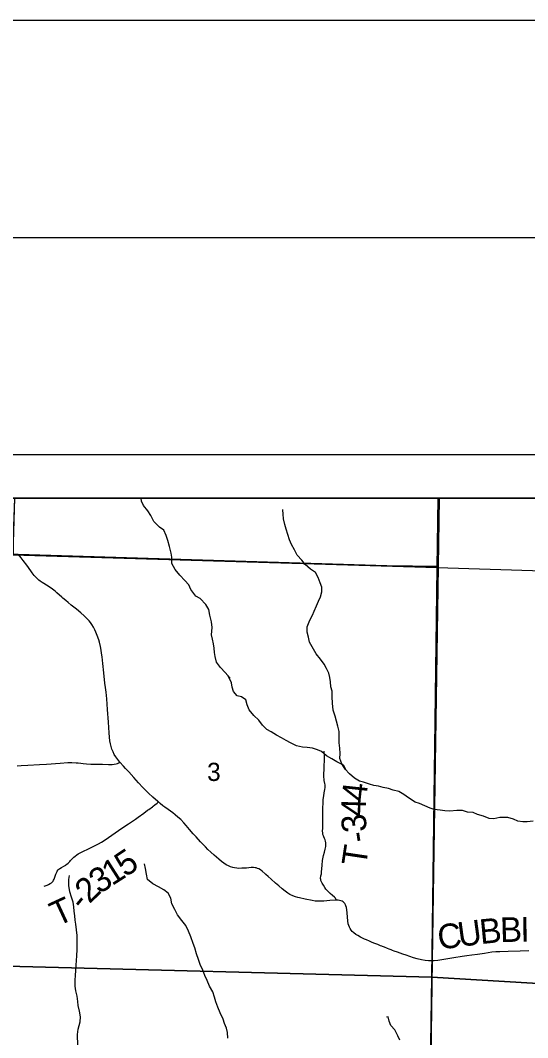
# Model space of a CAD drawing. Extents: x 0 to 34, y 0 to 22.
# Drawn here: x 24.137 to 25.305, y 19.658 to 22 of the extents above; entities that cross this region are included whole.
import ezdxf

# ---------------------------------------------------------------- set-up
doc = ezdxf.new("R2010")
doc.units = 0
for name, color, linetype in [('GM_X_Corporation', 7, 'Continuous'), ('GM_X_County_Road', 7, 'Continuous'), ('GM_X_County_Road_Text', 7, 'Continuous'), ('GM_X_Minor_River', 7, 'Continuous'), ('GM_X_Section_Text', 7, 'Continuous'), ('GM_X_Township_Road', 7, 'Continuous'), ('GM_X_Township_Road_Text', 7, 'Continuous'), ('SH_Border', 7, 'Continuous'), ('SH_Cut_Line', 7, 'Continuous'), ('SH_Data', 7, 'Continuous')]:
    doc.layers.add(name, color=color, linetype=linetype)

msp = doc.modelspace()

# ---------------------------------------------------------------- linework, layer by layer
at = {"layer": 'GM_X_Corporation'}
for points in [[(30.3167, 20.9), (23.5167, 20.9), (23.5167, 14.7114), (24.6586, 14.6808), (24.6805, 14.6799), (26.0522, 14.6391), (26.4447, 14.6283), (26.4468, 14.6272), (26.4498, 14.6263), (26.4544, 14.6257), (26.5226, 14.6248), (26.5325, 14.6248), (26.5616, 14.6241), (26.5684, 14.624), (26.5727, 14.624), (26.5813, 14.6239), (26.5991, 14.6234), (26.6128, 14.6229), (26.6208, 14.6225), (26.6337, 14.622), (26.643, 14.6216), (26.6535, 14.621), (27.01, 14.6164)], [(30.3167, 20.9), (25.1014, 20.9), (25.0988, 20.7425), (25.0847, 19.8351), (25.0701, 18.7696), (25.0668, 18.5474), (25.0619, 17.7438), (25.4012, 17.7333), (26.0747, 17.7146), (26.0759, 17.6934), (26.0745, 17.4524), (26.0677, 16.948), (26.0646, 16.863), (26.0683, 16.6823), (26.3378, 16.673), (27.0694, 16.6556)], [(26.0759, 17.6934), (26.0747, 17.7146), (25.4012, 17.7333), (25.0619, 17.7438), (25.0668, 18.5474), (25.0701, 18.7696), (25.0847, 19.8351), (25.0988, 20.7425), (24.9808, 20.7443), (24.1323, 20.7702), (24.1208, 20.7707), (23.5167, 20.7862), (23.5167, 14.7114)]]:
    msp.add_lwpolyline(points, dxfattribs=at)
for points in [[(25.0987, 20.9), (24.1235, 20.9), (24.1192, 20.7694), (25.0966, 20.7402)], [(25.1014, 20.9), (24.124, 20.9), (24.1207, 20.7979), (24.1208, 20.7707), (24.1323, 20.7702), (24.9808, 20.7443), (25.0988, 20.7425)], [(26.1019, 20.9), (25.0987, 20.9), (25.0966, 20.7402), (26.0969, 20.7089)], [(24.0752, 20.7675), (24.1192, 20.7694), (25.0966, 20.7402), (25.0844, 19.7972), (24.0758, 19.8228)], [(26.0969, 20.7089), (26.1216, 20.708), (26.1009, 19.7362), (25.0844, 19.7972), (25.0966, 20.7402)], [(25.0844, 19.7972), (25.0685, 18.7697), (24.0555, 18.7938), (24.0758, 19.8228)], [(25.0844, 19.7972), (26.1009, 19.7362), (26.0916, 18.7368), (25.0685, 18.7697)]]:
    msp.add_lwpolyline(points, close=True, dxfattribs=at)
at = {"layer": 'GM_X_County_Road'}
for points in [[(24.366, 20.2916), (24.3612, 20.2977), (24.3589, 20.3009), (24.3569, 20.304), (24.3534, 20.3099), (24.3504, 20.3159), (24.3478, 20.3221), (24.3458, 20.3279), (24.3443, 20.3339), (24.343, 20.3411), (24.342, 20.3497), (24.3412, 20.3596), (24.3405, 20.372), (24.3399, 20.3838), (24.338, 20.4129), (24.336, 20.4376), (24.3343, 20.453), (24.3331, 20.4635), (24.3319, 20.474), (24.3293, 20.4975), (24.3271, 20.5191), (24.3252, 20.5345), (24.3242, 20.5432), (24.3232, 20.5499), (24.3214, 20.5585), (24.319, 20.5681), (24.3174, 20.5735), (24.3141, 20.5836), (24.3111, 20.5912), (24.3088, 20.5963), (24.3055, 20.6024), (24.3016, 20.6088), (24.2983, 20.6134), (24.2952, 20.6173), (24.2901, 20.6228), (24.2843, 20.6285), (24.2765, 20.6355), (24.2664, 20.6438), (24.2544, 20.6536), (24.2472, 20.6594), (24.2414, 20.664), (24.2352, 20.6692), (24.2324, 20.6717), (24.221, 20.6821), (24.2172, 20.6853), (24.2113, 20.69), (24.2059, 20.6941), (24.1976, 20.6997), (24.1912, 20.7035), (24.1875, 20.7058), (24.1828, 20.7087), (24.1794, 20.7113), (24.1758, 20.7145), (24.1732, 20.7171), (24.1692, 20.7217), (24.1643, 20.728), (24.1543, 20.7423), (24.1513, 20.7462), (24.1499, 20.7483), (24.1482, 20.7502), (24.1445, 20.7552), (24.1437, 20.7561), (24.1386, 20.7624), (24.1325, 20.7697)], [(24.4547, 20.2003), (24.4533, 20.2014), (24.4422, 20.2113), (24.4323, 20.2206), (24.4261, 20.2267), (24.4192, 20.2338), (24.4091, 20.2446), (24.3983, 20.2565), (24.3865, 20.2693), (24.3792, 20.2775), (24.3743, 20.2829), (24.366, 20.2916)], [(24.8645, 19.9742), (24.8496, 19.9733), (24.836, 19.972), (24.8267, 19.9716), (24.8218, 19.9716), (24.8157, 19.972), (24.8084, 19.973), (24.7926, 19.9763), (24.7793, 19.9793), (24.7757, 19.9803), (24.7705, 19.9819), (24.7641, 19.9844), (24.7574, 19.9874), (24.7527, 19.9902), (24.7468, 19.9946), (24.7396, 20.0005), (24.7321, 20.0069), (24.7247, 20.0135), (24.7145, 20.0227), (24.7075, 20.0289), (24.7024, 20.0334), (24.7005, 20.035), (24.6935, 20.0412), (24.6899, 20.0439), (24.6861, 20.0462), (24.6832, 20.0474), (24.6801, 20.0484), (24.6776, 20.0488), (24.6738, 20.0491), (24.6687, 20.049), (24.6575, 20.0481), (24.647, 20.0475), (24.6402, 20.0474), (24.6354, 20.0478), (24.6299, 20.0486), (24.6258, 20.0496), (24.6211, 20.0512), (24.616, 20.0533), (24.6111, 20.0558), (24.6053, 20.0593), (24.5998, 20.0632), (24.5936, 20.0683), (24.5829, 20.0777), (24.5756, 20.0845), (24.569, 20.091), (24.5629, 20.0972), (24.5521, 20.1083), (24.5416, 20.1198), (24.5351, 20.1272), (24.5266, 20.1371), (24.5189, 20.1461), (24.5131, 20.1525), (24.5062, 20.1597), (24.4998, 20.1656), (24.4937, 20.1709), (24.4879, 20.1755), (24.4773, 20.1829), (24.4698, 20.1883), (24.4653, 20.1917), (24.4586, 20.197), (24.4547, 20.2003)], [(25.3077, 19.8572), (25.2872, 19.8567), (25.2599, 19.8561), (25.2407, 19.8555), (25.2314, 19.8549), (25.2226, 19.8541), (25.2136, 19.8528), (25.2058, 19.8516), (25.1893, 19.8493), (25.1764, 19.8474), (25.1647, 19.8456), (25.1542, 19.8442), (25.1352, 19.8413), (25.126, 19.8399), (25.1076, 19.8368), (25.0978, 19.8354), (25.0898, 19.8347), (25.0849, 19.8345), (25.0831, 19.8345), (25.0763, 19.8347), (25.069, 19.8354), (25.0604, 19.8368), (25.0508, 19.8391), (25.0419, 19.8417), (25.0336, 19.8443), (25.0249, 19.8474), (25.0178, 19.8498), (25.005, 19.8543), (24.9975, 19.857), (24.994, 19.8584), (24.9922, 19.859), (24.9905, 19.8597), (24.9859, 19.8615), (24.9819, 19.8631), (24.975, 19.8658), (24.971, 19.8675), (24.9693, 19.8681), (24.9664, 19.8692), (24.9646, 19.8699), (24.96, 19.8717), (24.9554, 19.8735), (24.9508, 19.8754), (24.9451, 19.8777), (24.9405, 19.8796), (24.9336, 19.8825), (24.9291, 19.8845), (24.9258, 19.8861), (24.9197, 19.8891), (24.9137, 19.8924), (24.909, 19.8953), (24.9046, 19.8986), (24.9011, 19.9019), (24.8983, 19.9051), (24.896, 19.9087), (24.8944, 19.9119), (24.893, 19.9159), (24.892, 19.92), (24.891, 19.9267), (24.8902, 19.9347), (24.8894, 19.9447), (24.8887, 19.9515), (24.8877, 19.9571), (24.8866, 19.9608), (24.8854, 19.9637), (24.8836, 19.9665), (24.8819, 19.9684), (24.8799, 19.9701), (24.8776, 19.9715), (24.8746, 19.9728), (24.872, 19.9737), (24.8686, 19.9742), (24.8645, 19.9742)]]:
    msp.add_lwpolyline(points, dxfattribs=at)
at = {"layer": 'GM_X_Minor_River'}
for points in [[(24.6198, 20.4855), (24.6083, 20.4983), (24.5976, 20.51), (24.5884, 20.5225), (24.5857, 20.535), (24.5841, 20.5444), (24.5833, 20.5543), (24.5813, 20.5642), (24.579, 20.5748), (24.577, 20.585), (24.5788, 20.6021), (24.5768, 20.6154), (24.5733, 20.6306), (24.5709, 20.6435), (24.5644, 20.6552), (24.5506, 20.6688), (24.5411, 20.6744), (24.5292, 20.6891), (24.525, 20.7001), (24.5155, 20.7099), (24.5044, 20.7224), (24.4933, 20.7352), (24.486, 20.7496), (24.4859, 20.764), (24.4843, 20.7735), (24.4804, 20.7887), (24.4765, 20.8023), (24.4726, 20.8137), (24.4676, 20.8258), (24.457, 20.8333), (24.4444, 20.8458), (24.4371, 20.8598), (24.4302, 20.8704), (24.4206, 20.8832), (24.4163, 20.8931), (24.4155, 20.9)], [(24.8307, 20.6841), (24.8314, 20.6951), (24.8271, 20.7049), (24.8229, 20.7174), (24.8167, 20.7287), (24.8053, 20.7361), (24.7927, 20.747), (24.7847, 20.7571), (24.7744, 20.7688), (24.7679, 20.7805), (24.7613, 20.7929), (24.7563, 20.8038), (24.7524, 20.8163), (24.7489, 20.8284), (24.7462, 20.8394), (24.7426, 20.8522), (24.7418, 20.8628), (24.7409, 20.8731), (24.7413, 20.8738)], [(25.3174, 20.156), (25.3038, 20.1547), (25.2939, 20.1542), (25.2818, 20.1564), (25.272, 20.1608), (25.2591, 20.1645), (25.2406, 20.1643), (25.227, 20.1615), (25.216, 20.1625), (25.2035, 20.1673), (25.1895, 20.1713), (25.1796, 20.1761), (25.166, 20.1764), (25.1546, 20.1804), (25.1418, 20.1807), (25.1255, 20.1794), (25.1145, 20.18), (25.1032, 20.1814), (25.0899, 20.1832), (25.0801, 20.1857), (25.0679, 20.1916), (25.0562, 20.1964), (25.046, 20.1994), (25.0307, 20.2098), (25.0197, 20.2177), (25.0079, 20.224), (24.9954, 20.2273), (24.9844, 20.2309), (24.9719, 20.2338), (24.9617, 20.2368), (24.9507, 20.2385), (24.9405, 20.2415), (24.9272, 20.2459), (24.9174, 20.2484), (24.9063, 20.2551), (24.8949, 20.2652), (24.885, 20.2757), (24.8769, 20.2882), (24.8727, 20.3002), (24.873, 20.312), (24.8721, 20.3241), (24.8712, 20.3366), (24.8707, 20.3499), (24.8706, 20.3624), (24.8682, 20.3745), (24.8647, 20.3866), (24.862, 20.3975), (24.857, 20.4119), (24.8557, 20.4278), (24.8548, 20.4425), (24.8547, 20.455), (24.8519, 20.4653), (24.8511, 20.4766), (24.8495, 20.4865), (24.8471, 20.497), (24.8421, 20.5072), (24.8364, 20.5174), (24.8276, 20.5287), (24.818, 20.5411), (24.8122, 20.552), (24.803, 20.5682), (24.8006, 20.5795), (24.7971, 20.5916), (24.7974, 20.6038), (24.8037, 20.6186), (24.8093, 20.6304), (24.8133, 20.6399), (24.8189, 20.6521), (24.823, 20.6628), (24.8278, 20.6723), (24.8307, 20.6841)], [(24.8859, 20.2748), (24.8808, 20.2852), (24.8652, 20.293), (24.8538, 20.2993), (24.8416, 20.3067), (24.8302, 20.3161), (24.8207, 20.3202), (24.8097, 20.3242), (24.7976, 20.3256), (24.7866, 20.3266), (24.773, 20.3295), (24.759, 20.3362), (24.7487, 20.3418), (24.7384, 20.3481), (24.727, 20.354), (24.7141, 20.3619), (24.7046, 20.3671), (24.6947, 20.3772), (24.6859, 20.3889), (24.6745, 20.3997), (24.6634, 20.4125), (24.6595, 20.4238), (24.656, 20.4352), (24.6465, 20.4426), (24.6363, 20.4448), (24.6275, 20.4546), (24.6244, 20.4644), (24.6228, 20.4742), (24.6153, 20.4905), (24.6143, 20.4889)], [(24.6149, 19.6563), (24.6136, 19.6696), (24.6113, 19.6794), (24.6071, 19.69), (24.6036, 19.7003), (24.597, 19.7146), (24.5916, 19.7279), (24.5874, 19.74), (24.5843, 19.751), (24.58, 19.7627), (24.5727, 19.7764), (24.5673, 19.7892), (24.5619, 19.801), (24.5569, 19.8131), (24.5512, 19.8259), (24.5469, 19.8373), (24.5426, 19.8502), (24.5388, 19.8646), (24.5345, 19.8744), (24.5295, 19.8896), (24.5245, 19.9024), (24.5179, 19.9157), (24.5088, 19.9274), (24.4988, 19.9406), (24.4923, 19.9523), (24.4861, 19.9656), (24.4834, 19.9785), (24.4772, 19.9902), (24.4673, 19.9977), (24.4552, 20.0045), (24.4418, 20.0116), (24.43, 20.0218), (24.4277, 20.0339), (24.4249, 20.0472), (24.4226, 20.0581)], [(24.2696, 19.6392), (24.2687, 19.665), (24.2705, 19.6771), (24.2745, 19.6939), (24.2752, 19.7053), (24.2736, 19.7189), (24.2705, 19.7314), (24.2693, 19.7409), (24.2681, 19.7527), (24.265, 19.7655), (24.263, 19.7758), (24.2633, 19.7891), (24.2643, 19.8016), (24.2646, 19.8115), (24.2653, 19.8251), (24.2664, 19.8346), (24.2674, 19.8464), (24.2681, 19.8597), (24.2679, 19.8927), (24.2666, 19.9056), (24.2647, 19.9189), (24.2631, 19.9284), (24.2623, 19.9382), (24.261, 19.9489), (24.2602, 19.9591), (24.2586, 19.9697), (24.2551, 19.9811), (24.2509, 19.9932), (24.2485, 20.008), (24.2484, 20.0217), (24.2502, 20.0312)], [(24.9991, 19.6752), (24.9896, 19.6857), (24.9857, 19.6955), (24.9837, 19.7054), (24.9796, 19.705)], [(25.0103, 19.6515), (25.0057, 19.6617), (24.9991, 19.6752)]]:
    msp.add_lwpolyline(points, dxfattribs=at)
at = {"layer": 'GM_X_Township_Road'}
for points in [[(24.8645, 19.9742), (24.8636, 19.9767), (24.8626, 19.9789), (24.8604, 19.9813), (24.8559, 19.9852), (24.8503, 19.9892), (24.8476, 19.9915), (24.8455, 19.9937), (24.8432, 19.9961), (24.8406, 19.9995), (24.8379, 20.0036), (24.8348, 20.0085), (24.8317, 20.0133), (24.8294, 20.0175), (24.8288, 20.0194), (24.8284, 20.0214), (24.8283, 20.0244), (24.8289, 20.0298), (24.8299, 20.0346), (24.8305, 20.0391), (24.8313, 20.0459), (24.8318, 20.0546), (24.8329, 20.0651), (24.8345, 20.0768), (24.8368, 20.085), (24.8386, 20.0917), (24.8399, 20.0974), (24.8402, 20.1004), (24.8402, 20.1027), (24.8404, 20.1061), (24.8396, 20.1101), (24.8385, 20.1129), (24.837, 20.1162), (24.8355, 20.1198), (24.8345, 20.1226), (24.8336, 20.1255), (24.833, 20.1286), (24.8328, 20.1335), (24.8331, 20.1394), (24.8331, 20.1517), (24.8333, 20.1847), (24.8338, 20.1996), (24.8344, 20.2051), (24.8356, 20.215), (24.8358, 20.2174), (24.8363, 20.2192), (24.8365, 20.2211), (24.8383, 20.229), (24.8389, 20.2333), (24.839, 20.2363), (24.8388, 20.2394), (24.8381, 20.243), (24.8365, 20.2495), (24.8361, 20.2525), (24.8361, 20.2538), (24.8359, 20.2562), (24.8357, 20.2635), (24.8361, 20.2764), (24.8364, 20.285), (24.8368, 20.2943), (24.837, 20.3057), (24.8365, 20.3171)], [(24.1301, 20.2835), (24.1388, 20.2841), (24.1543, 20.2853), (24.1809, 20.2868), (24.1976, 20.2876), (24.2286, 20.2894), (24.2463, 20.2909), (24.2555, 20.2912), (24.2654, 20.2906), (24.2703, 20.2901), (24.2765, 20.2895), (24.2813, 20.289), (24.2894, 20.2883), (24.2993, 20.2875), (24.3142, 20.2871), (24.3264, 20.2869), (24.3401, 20.2867), (24.3488, 20.2868), (24.3533, 20.2871), (24.3577, 20.2881), (24.3604, 20.2889), (24.3635, 20.2903), (24.366, 20.2916)], [(24.1916, 20.006), (24.1985, 20.0089), (24.2019, 20.0104), (24.2058, 20.0123), (24.2084, 20.014), (24.2103, 20.0156), (24.2124, 20.0178), (24.2137, 20.0199), (24.215, 20.0227), (24.2167, 20.0273), (24.219, 20.0337), (24.2208, 20.0384), (24.2222, 20.0411), (24.224, 20.0436), (24.2257, 20.0454), (24.2277, 20.0469), (24.2315, 20.049), (24.2375, 20.0521), (24.2416, 20.0548), (24.2421, 20.0553), (24.244, 20.0568), (24.2472, 20.0597), (24.2506, 20.0632), (24.2522, 20.0651), (24.255, 20.068), (24.257, 20.07), (24.2599, 20.0728), (24.2631, 20.0756), (24.2671, 20.0786), (24.2703, 20.0806), (24.273, 20.0821), (24.278, 20.0846), (24.2969, 20.0935), (24.3096, 20.0998), (24.3172, 20.1039), (24.3236, 20.1076), (24.332, 20.1129), (24.3477, 20.124), (24.3629, 20.1347), (24.3752, 20.143), (24.386, 20.1502), (24.4019, 20.1609), (24.408, 20.1652), (24.4211, 20.1746), (24.4301, 20.1811), (24.4327, 20.1829), (24.4357, 20.185), (24.4382, 20.1868), (24.4412, 20.1889), (24.4431, 20.1904), (24.4469, 20.1936), (24.4518, 20.1978), (24.4547, 20.2003)]]:
    msp.add_lwpolyline(points, dxfattribs=at)
at = {"layer": 'SH_Border'}
msp.add_lwpolyline([(1.5, 21.5), (33.5, 21.5), (33.5, 0.5), (1.5, 0.5)], close=True, dxfattribs=at)
at = {"layer": 'SH_Cut_Line'}
msp.add_lwpolyline([(0, 0), (34, 0), (34, 22), (0, 22)], close=True, dxfattribs=at)
at = {"layer": 'SH_Data'}
for points in [[(23.4167, 21), (30.4167, 21), (30.4167, 14), (23.4167, 14)], [(23.5167, 20.9), (30.3167, 20.9), (30.3167, 14.1), (23.5167, 14.1)]]:
    msp.add_lwpolyline(points, close=True, dxfattribs=at)

# ---------------------------------------------------------------- texts
at = {"layer": 'GM_X_County_Road_Text'}
for s, rotation, p in [('B', 1.5282, (25.2419, 19.8774)), ('I', 0.7416, (25.2884, 19.8786)), ('C', 7.8657, (25.1014, 19.8598)), ('U', 7.7391, (25.1476, 19.8662)), ('B', 5.6135, (25.1966, 19.8729))]:
    msp.add_text(s, height=0.0568, rotation=rotation, dxfattribs=at).set_placement(p)
at = {"layer": 'GM_X_Section_Text'}
msp.add_text('3', height=0.0419, rotation=0, dxfattribs=at).set_placement((24.567, 20.2486))
at = {"layer": 'GM_X_Township_Road_Text'}
for s, rotation, p in [('4', 83.8842, (24.9328, 20.1997)), ('4', 88.1783, (24.9318, 20.1658)), ('3', 95.7914, (24.9352, 20.133)), ('-', 98.6911, (24.9387, 20.1107)), ('T', 81.5568, (24.9325, 20.0502)), ('5', 34.0872, (24.3788, 20.0258)), ('1', 32.5526, (24.3479, 20.0061)), ('3', 33.1445, (24.3188, 19.987)), ('2', 44.6118, (24.2962, 19.9643)), ('T', 24.8628, (24.2221, 19.9128)), ('-', 50.4837, (24.2824, 19.9475))]:
    msp.add_text(s, height=0.0568, rotation=rotation, dxfattribs=at).set_placement(p)

doc.saveas('drawing.dxf')
